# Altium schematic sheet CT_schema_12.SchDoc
size 389 x 385 mm
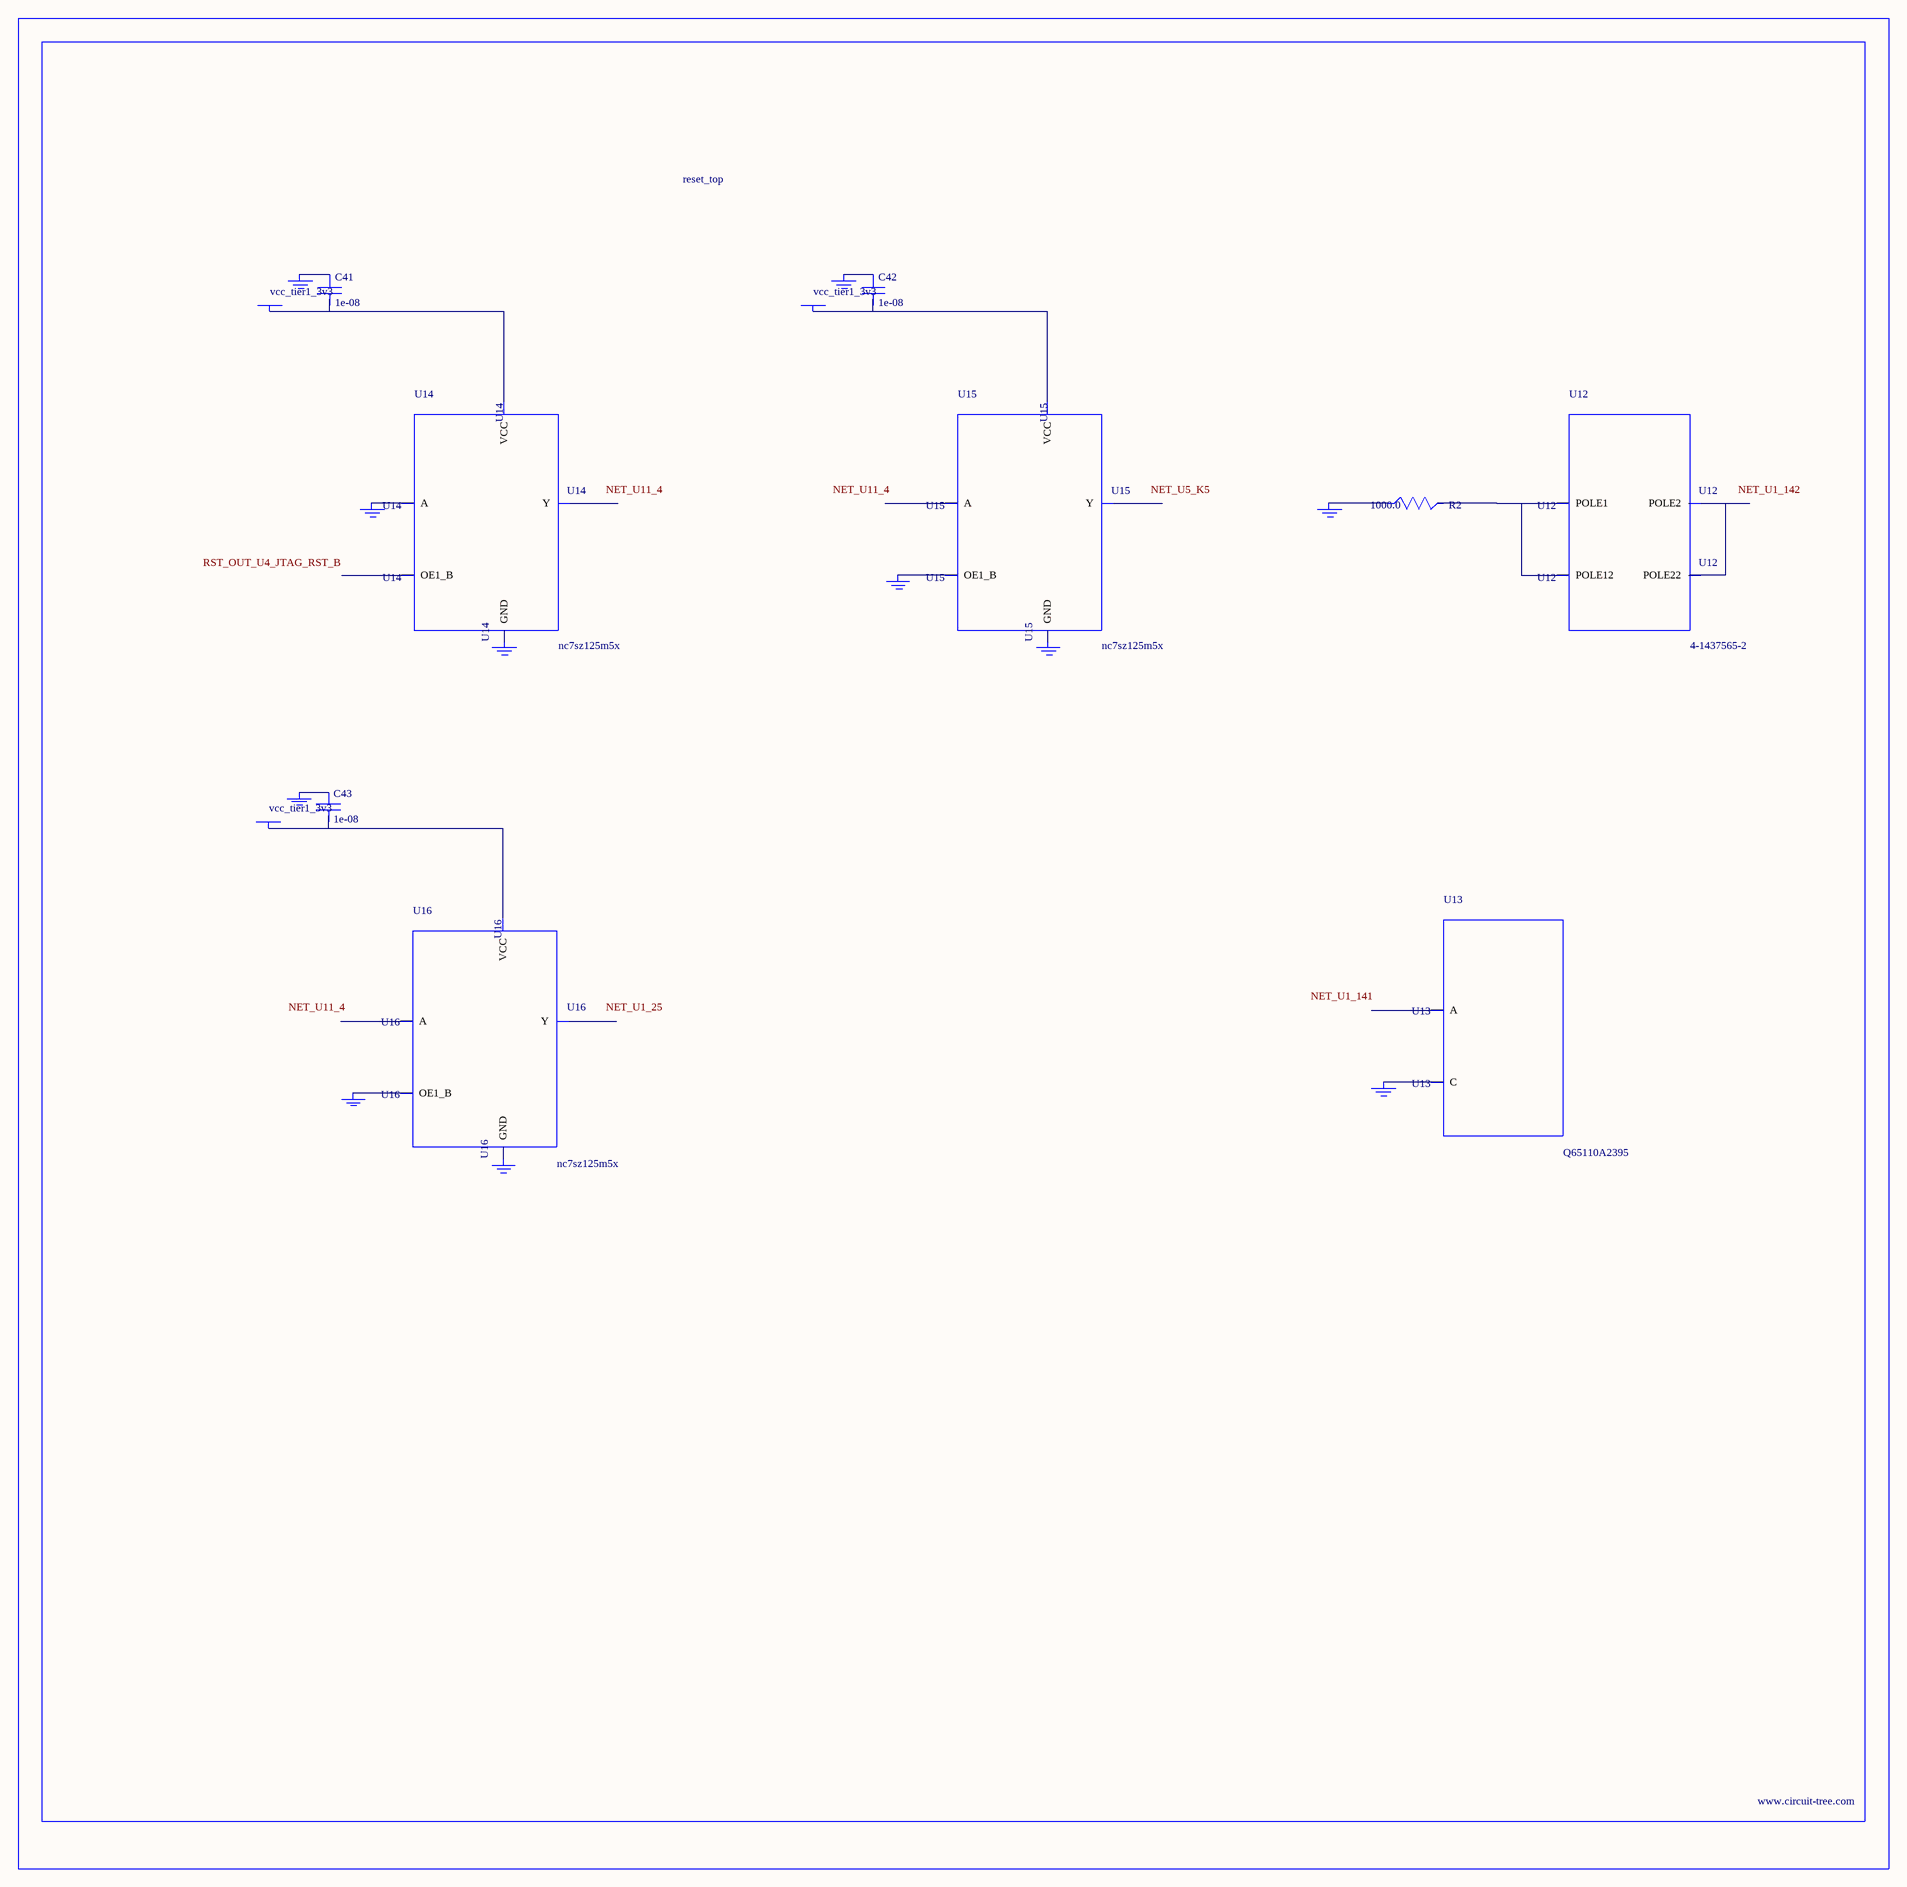
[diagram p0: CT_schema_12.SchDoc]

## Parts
BORDER11  (no value)
C41  1e-08  [C0402]
C42  1e-08  [C0402]
C43  1e-08  [C0402]
GND_INSTANCE_11_0  (no value)
GND_INSTANCE_11_1  (no value)
GND_INSTANCE_11_2  (no value)
GND_INSTANCE_11_3  (no value)
GND_INSTANCE_11_4  (no value)
GND_INSTANCE_11_5  (no value)
GND_INSTANCE_11_6  (no value)
GND_INSTANCE_11_7  (no value)
GND_INSTANCE_11_8  (no value)
GND_INSTANCE_11_9  (no value)
GND_INSTANCE_11_10  (no value)
POWER_INSTANCE_11_0  vcc_tier1_3v3
POWER_INSTANCE_11_1  vcc_tier1_3v3
POWER_INSTANCE_11_2  vcc_tier1_3v3
R2  1000.0  [R0603]
U12  4-1437565-2  [SW_4-1437565-2]
U13  Q65110A2395  [LGM67K-G1J2-24-Z]
U14  nc7sz125m5x  [NC7SZ125M5X]
U15  nc7sz125m5x  [NC7SZ125M5X]
U16  nc7sz125m5x  [NC7SZ125M5X]

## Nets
NetC41_1: C41.1 GND_INSTANCE_11_2.0(GND)
NetC41_2: C41.2 POWER_INSTANCE_11_0.0(PWR) U14.5(VCC)
NetC42_1: C42.1 GND_INSTANCE_11_5.0(GND)
NetC42_2: C42.2 POWER_INSTANCE_11_1.0(PWR) U15.5(VCC)
NetC43_1: C43.1 GND_INSTANCE_11_8.0(GND)
NetC43_2: C43.2 POWER_INSTANCE_11_2.0(PWR) U16.5(VCC)
NetGND_INSTANCE_11_0_0: GND_INSTANCE_11_0.0(GND) R2.1
NetGND_INSTANCE_11_1_0: GND_INSTANCE_11_1.0(GND) U13.C
NetGND_INSTANCE_11_3_0: GND_INSTANCE_11_3.0(GND) U14.2(A)
NetGND_INSTANCE_11_4_0: GND_INSTANCE_11_4.0(GND) U14.3(GND)
NetGND_INSTANCE_11_6_0: GND_INSTANCE_11_6.0(GND) U15.1(OE1_B)
NetGND_INSTANCE_11_7_0: GND_INSTANCE_11_7.0(GND) U15.3(GND)
NetGND_INSTANCE_11_9_0: GND_INSTANCE_11_9.0(GND) U16.1(OE1_B)
NetGND_INSTANCE_11_10_0: GND_INSTANCE_11_10.0(GND) U16.3(GND)
NetR2_2: R2.2 U12.1(POLE1) U12.2(POLE12)
NetU12_3: U12.3(POLE2) U12.4(POLE22)

Not connected (* = marked no-connect by the designer): U13 A; U14 1(OE1_B) 4(Y); U15 2(A) 4(Y); U16 2(A) 4(Y)

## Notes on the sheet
- Labels drawn without touching a wire or pin: NET_U1_25, NET_U1_141, NET_U1_142, NET_U5_K5, NET_U11_4, RST_OUT_U4_JTAG_RST_B

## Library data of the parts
BORDER11 = BORDER_PAGE11
C41-C43 = C0402C103K3RAC
GND_INSTANCE_11_0-GND_INSTANCE_11_10 = GND
POWER_INSTANCE_11_0-POWER_INSTANCE_11_2 = PWR
R2 = RC0603JR-071KL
